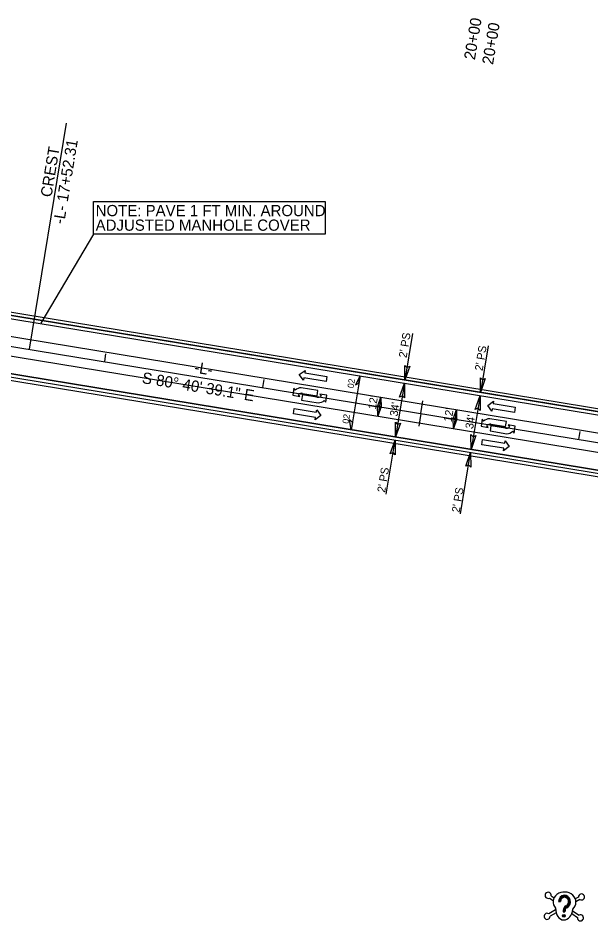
# Model space of a CAD drawing. Extents: x 1755545 to 1761252, y 736169 to 737766.
# Drawn here: x 1756439 to 1756796, y 736735 to 737298 of the extents above; entities that cross this region are included whole.
import ezdxf

# ---------------------------------------------------------------- set-up
doc = ezdxf.new("R2010")
doc.units = 0
for name, color, linetype in [('Default', 7, 'Continuous'), ('Exist Contamination Potential Cell', 7, 'Continuous'), ('Exist Cultural Church Label', 7, 'Continuous'), ('Old_Level_15', 7, 'Continuous'), ('Prop Dimension', 7, 'Continuous'), ('Prop Horizontal Alignment', 7, 'Continuous'), ('Prop Horizontal Alignment Direction Label', 7, 'Continuous'), ('Prop Horizontal Alignment Tick Label', 7, 'Continuous'), ('Prop Horizontal Alignment Tick Large', 7, 'Continuous'), ('Prop Horizontal Alignment Tick Small', 7, 'Continuous'), ('Prop Lane Arrow CELL', 7, 'Continuous'), ('Prop Lane Lines', 7, 'Continuous'), ('Prop Paved Shoulder', 7, 'Continuous'), ('Prop Shade Light', 7, 'Continuous'), ('Prop Superelevation Label', 7, 'Continuous'), ('Prop Terminator CELL', 7, 'Continuous'), ('Scratch_Level_6', 7, 'Continuous')]:
    doc.layers.add(name, color=color, linetype=linetype)

msp = doc.modelspace()

# ---------------------------------------------------------------- linework, layer by layer
at = {"layer": 'Default'}
for p, q in [((1756771.52, 736750.29), (1756773.4, 736748.98)), ((1756788.56, 736749.46), (1756786.56, 736748.34)), ((1756770.5, 736748.83), (1756772.82, 736747.21)), ((1756776.21, 736746.71), (1756777.34, 736746.66)), ((1756779.76, 736744.05), (1756779.76, 736744.05)), ((1756789.43, 736747.91), (1756786.97, 736746.52)), ((1756774.33, 736741.46), (1756770.02, 736739.03)), ((1756774.64, 736739.59), (1756770.9, 736737.48)), ((1756779.05, 736741.21), (1756779, 736740.22)), ((1756779, 736740.22), (1756780.13, 736740.16)), ((1756779.21, 736741.21), (1756779.16, 736740.21)), ((1756779.37, 736741.2), (1756779.33, 736740.2)), ((1756779.54, 736741.19), (1756779.49, 736740.2)), ((1756779.7, 736741.18), (1756779.65, 736740.19)), ((1756779.86, 736741.17), (1756779.81, 736740.18)), ((1756780.02, 736741.17), (1756779.97, 736740.17)), ((1756780.18, 736741.16), (1756780.13, 736740.16)), ((1756784.41, 736739.11), (1756787.94, 736736.65)), ((1756784.91, 736740.94), (1756788.96, 736738.12))]:
    msp.add_line(p, q, dxfattribs=at)
for radius in [0.81, 0.63, 0.446, 0.266, 0.0863]:
    msp.add_circle((1756779.49, 736737.73), radius, dxfattribs=at)
for centre, start, end in [((1756769.64, 736750.52), 353.1242, 297.0327), ((1756790.45, 736749.51), 237.4204, 181.3289), ((1756769, 736737.43), 57.4204, 1.3289), ((1756789.82, 736736.43), 173.1242, 117.0327)]:
    msp.add_arc(centre, 1.9, start, end, dxfattribs=at)
for centre, major_axis, ratio, start_param, end_param in [((1756779.86, 736746.3), (7.1, -0.34), 0.885014, 5.564242, 10.143721), ((1756779.88, 736746.53), (0.2, 4.08), 0.9, 3.567618, 7.853982), ((1756779.88, 736746.53), (0.19, 3.9), 0.9, 3.567618, 7.853982), ((1756779.88, 736746.53), (0.18, 3.72), 0.9, 3.567618, 7.853982), ((1756779.88, 736746.53), (0.17, 3.54), 0.9, 3.567618, 7.853982), ((1756779.88, 736746.53), (0.16, 3.36), 0.9, 3.567618, 7.853982), ((1756779.88, 736746.53), (0.15, 3.18), 0.9, 3.567618, 7.853982), ((1756779.88, 736746.53), (0.15, 3), 0.9, 3.567618, 7.853982), ((1756779.88, 736746.53), (0.14, 2.82), 0.9, 3.567618, 7.853982), ((1756781.8, 736741.08), (0.15, 3.06), 0.9, 0.426026, 1.570796), ((1756781.8, 736741.08), (0.14, 2.88), 0.9, 0.426026, 1.570796), ((1756781.8, 736741.08), (0.13, 2.7), 0.9, 0.426026, 1.570796), ((1756781.8, 736741.08), (0.12, 2.52), 0.9, 0.426026, 1.570796), ((1756779.67, 736742.23), (-0.34, -7.1), 0.752542, 4.722735, 7.843636), ((1756781.8, 736741.08), (0.11, 2.34), 0.9, 0.426026, 1.570796), ((1756781.8, 736741.08), (0.1, 2.16), 0.9, 0.426026, 1.570796), ((1756781.8, 736741.08), (0.1, 1.98), 0.9, 0.426026, 1.570796), ((1756781.8, 736741.08), (0.09, 1.8), 0.9, 0.426026, 1.570796)]:
    msp.add_ellipse(centre, major_axis=major_axis, ratio=ratio, start_param=start_param, end_param=end_param, dxfattribs=at)
at = {"layer": 'Exist Contamination Potential Cell'}
for p, q in [((1756210.53, 737147.44), (1756991.88, 737019.17)), ((1756205.02, 737113.89), (1756986.38, 736985.62))]:
    msp.add_line(p, q, dxfattribs=at)
at = {"layer": 'Exist Cultural Church Label'}
for points in [[(1756652.22, 737074.93), (1756649.27, 737069.34), (1756651.47, 737070.37)], [(1756646.71, 737041.38), (1756645.71, 737047.63), (1756647.46, 737045.95)]]:
    msp.add_lwpolyline(points, close=True, dxfattribs=at)
at = {"layer": 'Old_Level_15'}
msp.add_line((1756445.76, 737091.6), (1756468.95, 737232.85), dxfattribs=at)
at = {"layer": 'Prop Dimension'}
for p, q in [((1756485.78, 737163.51), (1756452.83, 737107.91)), ((1756685.01, 737101.45), (1756680.23, 737072.36)), ((1756732.2, 737093.7), (1756727.43, 737064.61)), ((1756679.91, 737070.39), (1756674.4, 737036.84)), ((1756665.24, 737061.65), (1756663.29, 737049.81)), ((1756727.11, 737062.64), (1756721.6, 737029.09)), ((1756712.43, 737053.9), (1756710.49, 737042.06)), ((1756668.52, 737001.02), (1756674.08, 737034.86)), ((1756714.98, 736988.77), (1756721.27, 737027.12))]:
    msp.add_line(p, q, dxfattribs=at)
msp.add_lwpolyline([(1756485.78, 737183.9), (1756630.53, 737183.9), (1756630.53, 737163.51), (1756485.78, 737163.51)], close=True, dxfattribs=at)
at = {"layer": 'Prop Horizontal Alignment'}
msp.add_line((1756207.78, 737130.67), (1757104.78, 736983.41), dxfattribs=at)
at = {"layer": 'Prop Horizontal Alignment Tick Large'}
for q in [(1756691.43, 737059.38), (1756688.84, 737043.59)]:
    msp.add_line((1756690.13, 737051.48), q, dxfattribs=at)
at = {"layer": 'Prop Horizontal Alignment Tick Small'}
for p, q in [((1756492.77, 737083.88), (1756493.58, 737088.81)), ((1756591.45, 737067.68), (1756592.26, 737072.62)), ((1756788.81, 737035.28), (1756789.62, 737040.22))]:
    msp.add_line(p, q, dxfattribs=at)
at = {"layer": 'Prop Lane Arrow CELL'}
for p, q in [((1756614.29, 737075.76), (1756617.92, 737078.41)), ((1756617.92, 737078.41), (1756617.67, 737076.93)), ((1756617.67, 737076.93), (1756631.49, 737074.66)), ((1756616.9, 737072.2), (1756614.29, 737075.76)), ((1756617.14, 737073.68), (1756616.9, 737072.2)), ((1756630.96, 737071.41), (1756617.14, 737073.68)), ((1756631.49, 737074.66), (1756630.96, 737071.41)), ((1756610.88, 737067.23), (1756610.16, 737062.84)), ((1756611.79, 737066.02), (1756610.88, 737067.23)), ((1756625.95, 737065.82), (1756615.54, 737067.53)), ((1756625.41, 737062.57), (1756625.95, 737065.82)), ((1756610.16, 737062.84), (1756614.6, 737062.11)), ((1756614.6, 737062.11), (1756613.73, 737063.32)), ((1756616.29, 737063.15), (1756615.75, 737059.9)), ((1756615.75, 737059.9), (1756626.16, 737058.19)), ((1756625.32, 737061.67), (1756616.29, 737063.15)), ((1756616.38, 737064.05), (1756625.41, 737062.57)), ((1756631.54, 737062.83), (1756627.1, 737063.61)), ((1756627.1, 737063.61), (1756627.97, 737062.4)), ((1756629.91, 737059.7), (1756630.77, 737058.5)), ((1756630.77, 737058.5), (1756631.54, 737062.83)), ((1756610.56, 737051.31), (1756611.09, 737054.56)), ((1756611.09, 737054.56), (1756624.91, 737052.29)), ((1756624.91, 737052.29), (1756625.15, 737053.78)), ((1756625.15, 737053.78), (1756627.76, 737050.21)), ((1756731.9, 737056.46), (1756735.53, 737059.11)), ((1756734.51, 737052.89), (1756731.9, 737056.46)), ((1756734.75, 737054.37), (1756734.51, 737052.89)), ((1756748.57, 737052.1), (1756734.75, 737054.37)), ((1756735.53, 737059.11), (1756735.29, 737057.63)), ((1756735.29, 737057.63), (1756749.1, 737055.36)), ((1756749.1, 737055.36), (1756748.57, 737052.1)), ((1756624.37, 737049.04), (1756610.56, 737051.31)), ((1756627.76, 737050.21), (1756624.13, 737047.56)), ((1756624.13, 737047.56), (1756624.37, 737049.04)), ((1756728.49, 737047.93), (1756727.77, 737043.54)), ((1756729.4, 737046.71), (1756728.49, 737047.93)), ((1756743.56, 737046.52), (1756733.15, 737048.23)), ((1756727.77, 737043.54), (1756732.21, 737042.81)), ((1756732.21, 737042.81), (1756731.34, 737044.01)), ((1756733.9, 737043.85), (1756733.36, 737040.59)), ((1756742.93, 737042.36), (1756733.9, 737043.85)), ((1756734, 737044.74), (1756743.02, 737043.26)), ((1756743.02, 737043.26), (1756743.56, 737046.52)), ((1756749.15, 737043.52), (1756744.72, 737044.3)), ((1756744.72, 737044.3), (1756745.58, 737043.09)), ((1756748.39, 737039.19), (1756749.15, 737043.52)), ((1756733.36, 737040.59), (1756743.78, 737038.88)), ((1756747.52, 737040.39), (1756748.39, 737039.19)), ((1756728.17, 737032), (1756728.7, 737035.26)), ((1756741.98, 737029.73), (1756728.17, 737032)), ((1756728.7, 737035.26), (1756742.52, 737032.99)), ((1756742.52, 737032.99), (1756742.76, 737034.47)), ((1756742.76, 737034.47), (1756745.37, 737030.9)), ((1756745.37, 737030.9), (1756741.74, 737028.25)), ((1756741.74, 737028.25), (1756741.98, 737029.73))]:
    msp.add_line(p, q, dxfattribs=at)
for centre, radius, start, end in [((1756615.46, 737062.27), 5.25, 89.3536, 134.6653), ((1756615.83, 737060.81), 3.28, 80.6775, 130.3357), ((1756625.85, 737064.88), 3.28, 260.6775, 310.3357), ((1756626.22, 737063.42), 5.25, 269.3536, 314.6653), ((1756733.07, 737042.96), 5.25, 89.3536, 134.6653), ((1756733.44, 737041.5), 3.28, 80.6775, 130.3357), ((1756743.47, 737045.58), 3.28, 260.6775, 310.3357), ((1756743.83, 737044.12), 5.25, 269.3536, 314.6653)]:
    msp.add_arc(centre, radius, start, end, dxfattribs=at)
at = {"layer": 'Prop Lane Lines'}
for p, q in [((1756208.75, 737136.59), (1756990.1, 737008.32)), ((1756220.43, 737122.51), (1756988.16, 736996.48))]:
    msp.add_line(p, q, dxfattribs=at)
at = {"layer": 'Prop Paved Shoulder'}
for p, q in [((1756210.85, 737149.41), (1756992.21, 737021.15)), ((1756204.7, 737111.92), (1756986.05, 736983.65))]:
    msp.add_line(p, q, dxfattribs=at)
at = {"layer": 'Prop Shade Light'}
for p, q in [((1756992.21, 737021.15), (1756210.85, 737149.41)), ((1756210.53, 737147.44), (1756991.88, 737019.17)), ((1756204.7, 737111.92), (1756986.05, 736983.65)), ((1756986.38, 736985.62), (1756205.02, 737113.89))]:
    msp.add_line(p, q, dxfattribs=at)
at = {"layer": 'Prop Superelevation Label'}
msp.add_line((1756652.22, 737074.93), (1756646.71, 737041.38), dxfattribs=at)
at = {"layer": 'Prop Terminator CELL'}
for points in [[(1756683.22, 737080.99), (1756680.23, 737072.36), (1756680.12, 737081.55), (1756681.51, 737080.16)], [(1756730.42, 737073.24), (1756727.43, 737064.61), (1756727.32, 737073.8), (1756728.71, 737072.41)], [(1756676.92, 737061.76), (1756679.91, 737070.39), (1756680.02, 737061.2), (1756678.63, 737062.59)], [(1756663.15, 737055.61), (1756665.24, 737061.65), (1756665.32, 737055.22), (1756664.34, 737056.19)], [(1756724.12, 737054.01), (1756727.11, 737062.64), (1756727.22, 737053.45), (1756725.83, 737054.84)], [(1756665.38, 737055.85), (1756663.29, 737049.81), (1756663.21, 737056.24), (1756664.19, 737055.27)], [(1756710.34, 737047.86), (1756712.43, 737053.9), (1756712.51, 737047.47), (1756711.54, 737048.45)], [(1756712.58, 737048.1), (1756710.49, 737042.06), (1756710.41, 737048.49), (1756711.38, 737047.52)], [(1756677.39, 737045.47), (1756674.4, 737036.84), (1756674.29, 737046.03), (1756675.68, 737044.63)], [(1756724.59, 737037.72), (1756721.6, 737029.09), (1756721.48, 737038.28), (1756722.88, 737036.89)], [(1756671.09, 737026.23), (1756674.08, 737034.86), (1756674.19, 737025.67), (1756672.8, 737027.07)], [(1756718.29, 737018.49), (1756721.27, 737027.12), (1756721.39, 737017.93), (1756719.99, 737019.32)]]:
    msp.add_lwpolyline(points, close=True, dxfattribs=at)
at = {"layer": 'Scratch_Level_6'}
for p, q in [((1756211.18, 737151.39), (1756992.53, 737023.12)), ((1756204.38, 737109.94), (1756985.73, 736981.68))]:
    msp.add_line(p, q, dxfattribs=at)

# ---------------------------------------------------------------- texts
at = {"layer": 'Old_Level_15'}
for s, p in [('CREST', (1756459.54, 737186.24)), ('-L- 17+52.31', (1756467.43, 737169.48))]:
    msp.add_text(s, height=7, rotation=80.6775, dxfattribs=at).set_placement(p)
at = {"layer": 'Prop Dimension'}
for s, p in [('NOTE: PAVE 1 FT MIN. AROUND ', (1756487.12, 737174.73)), ('ADJUSTED MANHOLE COVER', (1756487.12, 737165.63))]:
    msp.add_text(s, height=7, dxfattribs=at).set_placement(p)
for s, p in [("2' PS", (1756681.25, 737085.99)), ("2' PS", (1756728.71, 737077.86)), ("12'", (1756662.06, 737053.72)), ("34'", (1756675.58, 737049.42)), ("12'", (1756709.32, 737045.9)), ("34'", (1756722.77, 737041.6)), ("2' PS", (1756667.81, 737001.84)), ("2' PS", (1756714.32, 736989.33))]:
    msp.add_text(s, height=5, rotation=80.6775, dxfattribs=at).set_placement(p)
at = {"layer": 'Prop Horizontal Alignment Direction Label'}
for s, rotation, p in [('-L-', 350.6079, (1756548.36, 737077.04)), ('S 80%%d 40\' 39.1" E', 350.6775, (1756515.72, 737070.51))]:
    msp.add_text(s, height=7, rotation=rotation, dxfattribs=at).set_placement(p)
at = {"layer": 'Prop Horizontal Alignment Tick Label'}
for p in [(1756723.92, 737272.03), (1756735.22, 737269.06)]:
    msp.add_text('20+00', height=7, rotation=80.6079, dxfattribs=at).set_placement(p)
at = {"layer": 'Prop Superelevation Label'}
for p in [(1756648.17, 737067.06), (1756645.02, 737044.88)]:
    msp.add_text('02', height=4, rotation=80.6775, dxfattribs=at).set_placement(p)

doc.saveas('drawing.dxf')
